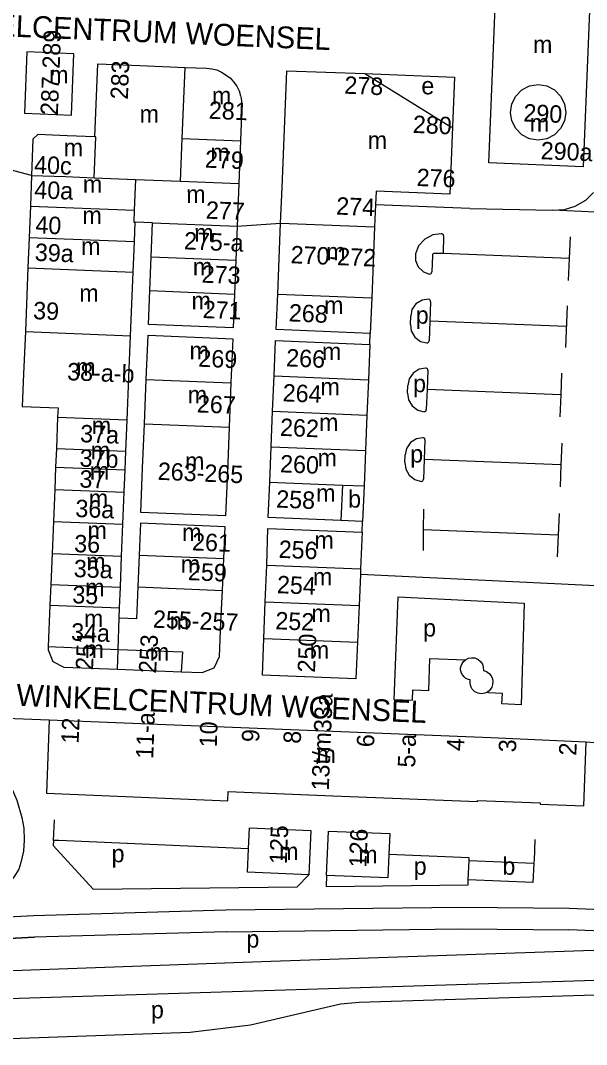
# Model space of a CAD drawing. Extents: x 159675 to 162108, y 386471 to 388472.
# Drawn here: x 161135.6 to 161265.7, y 386484.1 to 386719.4 of the extents above; entities that cross this region are included whole.
import ezdxf

# ---------------------------------------------------------------- set-up
doc = ezdxf.new("R2010")
doc.units = 0
for name, color, linetype in [('BLT_Basislijn', 7, 'Continuous'), ('BLT_Bebouwing', 7, 'Continuous'), ('BLT_Centroide', 7, 'Continuous'), ('BLT_Huisnummer', 7, 'Continuous'), ('BLT_Huisnummer_ tussenligend', 7, 'Continuous'), ('BLT_Huisnummer_reeks', 7, 'Continuous'), ('BLT_Onderverdeling_panden', 7, 'Continuous'), ('BLT_Straatnaam', 7, 'Continuous'), ('BLT_Vlakafsluiter', 7, 'Continuous')]:
    doc.layers.add(name, color=color, linetype=linetype)

msp = doc.modelspace()

# ---------------------------------------------------------------- linework, layer by layer
at = {"layer": 'BLT_Basislijn'}
for p, q in [((161238.9, 386676.16), (161217.2, 386677.02)), ((161261.9, 386669.65), (161261.7, 386664.65)), ((161261.7, 386664.65), (161232.74, 386665.8)), ((161230.28, 386665.38), (161230.15, 386661.59)), ((161261.7, 386664.65), (161261.5, 386659.66)), ((161229.86, 386654.77), (161229.69, 386650.33)), ((161261.27, 386653.85), (161260.89, 386644.21)), ((161225.23, 386649.56), (161225.3, 386651.45)), ((161229.69, 386650.33), (161229.51, 386645.78)), ((161261.08, 386649.08), (161229.69, 386650.33)), ((161215.89, 386644.97), (161216.01, 386647.46)), ((161228.89, 386639.5), (161228.74, 386639.5)), ((161229.21, 386639), (161229.04, 386634.56)), ((161259.98, 386638.33), (161259.78, 386633.34)), ((161224.58, 386633.74), (161224.65, 386635.55)), ((161229.04, 386634.56), (161228.86, 386629.99)), ((161259.78, 386633.34), (161229.04, 386634.56)), ((161259.78, 386633.34), (161259.58, 386628.34)), ((161228.24, 386623.5), (161228.08, 386623.51)), ((161228.56, 386623), (161228.38, 386618.51)), ((161260.02, 386622.26), (161259.82, 386617.26)), ((161223.93, 386617.82), (161224.02, 386619.57)), ((161228.38, 386618.51), (161228.2, 386613.99)), ((161259.82, 386617.26), (161228.38, 386618.51)), ((161259.82, 386617.26), (161259.62, 386612.26)), ((161228.24, 386607.13), (161228.19, 386602.36)), ((161259.38, 386606.13), (161259.18, 386601.13)), ((161214.14, 386601.81), (161214.24, 386604.3)), ((161228.19, 386602.36), (161228.15, 386597.59)), ((161259.18, 386601.13), (161228.19, 386602.36)), ((161259.18, 386601.13), (161258.98, 386596.14)), ((161339.15, 386586.03), (161213.72, 386592.09)), ((161143.21, 386531.02), (161143.43, 386535.77)), ((161261.72, 386515.44), (161288.25, 386514.48)), ((161288.04, 386509.49), (161261.61, 386510.44)), ((161182.92, 386510.03), (161138.83, 386508.8))]:
    msp.add_line(p, q, dxfattribs=at)
for points in [[(161214.78, 386707.15), (161235.37, 386706.31), (161234.9, 386694.91)], [(161257.9, 386675.78), (161260.62, 386675.93), (161263.1, 386676.69), (161265.52, 386678.11), (161267.33, 386679.85)], [(161238.9, 386676.16), (161257.9, 386675.78)], [(161232.31, 386670.39), (161230.35, 386670.13), (161228.5, 386669.15), (161227.1, 386667.59), (161226.36, 386665.76)], [(161232.63, 386670.31), (161232.55, 386670.34), (161232.47, 386670.36), (161232.39, 386670.38), (161232.31, 386670.39)], [(161232.86, 386669.88), (161232.74, 386665.8), (161230.82, 386665.86)], [(161232.86, 386669.88), (161232.85, 386670), (161232.8, 386670.12), (161232.73, 386670.23), (161232.63, 386670.31)], [(161226.36, 386665.76), (161226.36, 386664.25), (161227.01, 386662.75), (161228.2, 386661.63), (161229.62, 386661.11)], [(161230.82, 386665.86), (161230.63, 386665.84), (161230.44, 386665.74), (161230.32, 386665.57), (161230.28, 386665.38)], [(161229.62, 386661.11), (161229.81, 386661.14), (161229.98, 386661.24), (161230.1, 386661.41), (161230.15, 386661.59)], [(161229.4, 386655.31), (161227.91, 386655.15), (161226.48, 386654.3), (161225.56, 386652.94), (161225.3, 386651.45)], [(161229.86, 386654.77), (161229.85, 386654.96), (161229.75, 386655.14), (161229.59, 386655.27), (161229.4, 386655.31)], [(161225.23, 386649.56), (161225.4, 386648.05), (161226.22, 386646.62), (161227.55, 386645.64), (161229.02, 386645.29)], [(161229.02, 386645.29), (161229.2, 386645.33), (161229.36, 386645.44), (161229.47, 386645.6), (161229.51, 386645.78)], [(161228.74, 386639.5), (161227.25, 386639.25), (161225.87, 386638.38), (161224.96, 386637.03), (161224.65, 386635.55)], [(161229.21, 386639), (161229.22, 386639.16), (161229.15, 386639.31), (161229.03, 386639.44), (161228.89, 386639.5)], [(161224.58, 386633.74), (161224.77, 386632.23), (161225.59, 386630.81), (161226.92, 386629.84), (161228.39, 386629.49)], [(161228.39, 386629.49), (161228.56, 386629.53), (161228.73, 386629.64), (161228.83, 386629.81), (161228.86, 386629.99)], [(161228.08, 386623.51), (161226.6, 386623.26), (161225.23, 386622.39), (161224.32, 386621.04), (161224.02, 386619.57)], [(161228.56, 386623), (161228.56, 386623.16), (161228.5, 386623.32), (161228.38, 386623.44), (161228.24, 386623.5)], [(161223.93, 386617.82), (161224.15, 386616.32), (161224.96, 386614.9), (161226.25, 386613.9), (161227.71, 386613.47)], [(161227.71, 386613.47), (161227.9, 386613.5), (161228.07, 386613.62), (161228.18, 386613.8), (161228.2, 386613.99)], [(161222.33, 386586.94), (161221.39, 386563.4), (161225.71, 386563.21), (161225.79, 386565.61), (161229.44, 386565.47), (161229.71, 386572.83), (161237.86, 386572.51)], [(161222.33, 386586.94), (161251.38, 386585.5), (161250.65, 386562.18), (161246.26, 386562.36), (161246.36, 386564.74), (161243.15, 386564.92), (161243.01, 386565.15)], [(161243.01, 386565.15), (161242.69, 386564.97), (161242.3, 386564.82), (161241.94, 386564.74), (161241.55, 386564.71), (161241.13, 386564.74), (161240.78, 386564.83), (161240.44, 386564.96), (161240.06, 386565.18), (161239.75, 386565.43), (161239.43, 386565.79), (161239.17, 386566.23), (161239, 386566.7), (161238.93, 386567.13), (161238.94, 386567.57), (161238.98, 386567.87), (161238.55, 386567.97), (161237.99, 386568.22), (161237.54, 386568.57), (161237.11, 386569.13), (161236.88, 386569.65), (161236.77, 386570.21), (161236.77, 386570.62), (161236.86, 386571.1), (161237.08, 386571.64), (161237.42, 386572.12), (161237.86, 386572.51)], [(161237.86, 386572.51), (161238.56, 386572.87), (161239.27, 386572.99), (161240.02, 386572.92), (161240.78, 386572.59), (161241.31, 386572.15), (161241.76, 386571.48), (161241.97, 386570.8), (161241.98, 386570.06), (161242.7, 386569.81), (161243.31, 386569.39), (161243.79, 386568.8), (161244.08, 386568.15), (161244.19, 386567.49), (161244.12, 386566.8), (161243.94, 386566.25), (161243.66, 386565.78), (161243.31, 386565.39), (161243.01, 386565.15)], [(161143.21, 386531.02), (161143.15, 386529.87), (161152.35, 386519.82), (161199.21, 386520.34), (161201.89, 386523.11)], [(161188.01, 386529.08), (161144.39, 386530.97), (161143.21, 386531.02)], [(161253.55, 386525.76), (161253.73, 386526.41), (161253.92, 386531.23)], [(161238.72, 386526.37), (161238.75, 386527.03), (161220.28, 386527.8)], [(161205.97, 386522.96), (161205.86, 386520.4), (161238.48, 386520.79), (161238.53, 386521.93)], [(161182.82, 386515.03), (161236.89, 386515.67), (161261.72, 386515.44)], [(161109.08, 386511.16), (161122.36, 386512.92), (161138.63, 386513.79), (161182.82, 386515.03)], [(161182.92, 386510.03), (161236.89, 386510.67), (161261.61, 386510.44)], [(161182.96, 386510.03), (161138.83, 386508.8), (161122.82, 386507.94), (161105.19, 386505.61), (161094.47, 386504.99), (161082.47, 386504.72), (161064.43, 386504.23), (161051.3, 386504.09)], [(161093.24, 386504.92), (161105.19, 386505.61), (161122.82, 386507.94), (161138.83, 386508.8)], [(161093.48, 386499.86), (161114.65, 386500.44), (161193.13, 386503.27), (161323.46, 386507.7)], [(161324.17, 386500.57), (161157.3, 386495.37), (161093.79, 386493.39)], [(161094.24, 386484.13), (161174.59, 386486.96), (161188.48, 386488.62), (161209.16, 386493.49), (161213.42, 386493.85), (161324.27, 386497.31)]]:
    msp.add_lwpolyline(points, dxfattribs=at)
at = {"layer": 'BLT_Bebouwing'}
for p, q in [((161152.72, 386692.64), (161146.31, 386692.9)), ((161138.18, 386683.79), (161137.9, 386676.7)), ((161137.9, 386676.7), (161137.61, 386669.53)), ((161161.78, 386668.58), (161161.96, 386673.04)), ((161137.61, 386669.53), (161137.33, 386662.51)), ((161161.5, 386661.56), (161161.78, 386668.58)), ((161137.33, 386662.51), (161136.74, 386647.91)), ((161160.91, 386646.96), (161161.5, 386661.56)), ((161160.52, 386637.41), (161160.91, 386646.96)), ((161160.12, 386627.65), (161160.52, 386637.41)), ((161159.83, 386620.42), (161160.12, 386627.65)), ((161159.65, 386616.15), (161159.83, 386620.42)), ((161159.45, 386611.01), (161159.65, 386616.15)), ((161159.15, 386603.64), (161159.45, 386611.01)), ((161158.85, 386596.31), (161159.15, 386603.64)), ((161158.56, 386589.19), (161158.85, 386596.31)), ((161158.37, 386584.46), (161158.56, 386589.19)), ((161265.58, 386553.55), (161243.74, 386554.54)), ((161238.53, 386521.93), (161238.72, 386526.37)), ((161238.72, 386526.37), (161253.55, 386525.76))]:
    msp.add_line(p, q, dxfattribs=at)
msp.add_lwpolyline([(161243.24, 386686.66), (161245.41, 386739.49), (161267.09, 386738.62), (161264.93, 386685.78)], close=True, dxfattribs=at)
for points in [[(161137.07, 386712.16), (161136.52, 386698.08), (161147.34, 386697.64), (161147.89, 386711.74), (161137.07, 386712.16)], [(161152.72, 386692.64), (161153.4, 386709.39), (161163.05, 386709.01)], [(161163.05, 386709.01), (161173.43, 386708.6)], [(161173.43, 386708.6), (161178.38, 386708.41), (161179.56, 386708.28), (161180.72, 386707.99), (161181.82, 386707.52), (161183.78, 386706.18), (161184.19, 386705.74), (161184.6, 386705.3), (161185.31, 386704.25), (161185.84, 386703.18), (161186.21, 386702.04), (161186.31, 386701.45), (161186.41, 386700.86), (161186.45, 386699.8), (161186.14, 386691.69)], [(161196.26, 386694.39), (161196.8, 386707.78), (161214.78, 386707.15)], [(161214.78, 386707.15), (161234.48, 386694.93), (161234.9, 386694.91)], [(161254.58, 386691.9), (161252.61, 386692.21), (161250.84, 386693.11), (161249.43, 386694.52), (161248.52, 386696.3), (161248.21, 386698.26), (161248.52, 386700.23), (161249.43, 386702.01), (161250.84, 386703.41), (161252.61, 386704.32), (161254.58, 386704.63), (161256.54, 386704.32), (161258.32, 386703.41), (161259.73, 386702.01), (161260.63, 386700.23), (161260.94, 386698.26), (161260.63, 386696.3), (161259.73, 386694.52), (161258.32, 386693.11), (161256.54, 386692.21), (161254.58, 386691.9)], [(161195.72, 386681), (161196.26, 386694.39)], [(161234.9, 386694.91), (161234.27, 386679.43), (161217.32, 386680.12)], [(161146.31, 386692.9), (161139.63, 386693.17), (161138.47, 386692.09), (161138.18, 386683.79)], [(161186.14, 386691.69), (161185.77, 386681.9)], [(161185.77, 386681.9), (161185.39, 386672.09)], [(161195.39, 386672.83), (161195.72, 386681)], [(161217.32, 386680.12), (161217.2, 386677.02)], [(161217.2, 386677.02), (161216.99, 386671.96)], [(161165.98, 386672.88), (161161.96, 386673.04)], [(161165.67, 386665.09), (161165.98, 386672.88)], [(161195.06, 386664.67), (161195.39, 386672.83)], [(161185.39, 386672.09), (161185.1, 386664.31)], [(161216.99, 386671.96), (161216.66, 386663.8)], [(161165.35, 386657.31), (161165.67, 386665.09)], [(161185.1, 386664.31), (161184.8, 386656.52)], [(161194.73, 386656.51), (161195.06, 386664.67)], [(161216.66, 386663.8), (161216.34, 386655.64)], [(161184.8, 386656.52), (161184.5, 386648.74), (161165.04, 386649.53), (161165.35, 386657.31)], [(161194.4, 386648.34), (161194.73, 386656.51)], [(161216.34, 386655.64), (161216.01, 386647.46)], [(161136.74, 386647.91), (161136.33, 386638.18)], [(161164.52, 386636.89), (161164.93, 386647.04), (161184.4, 386646.25), (161183.99, 386636.1)], [(161216.01, 386647.46), (161194.4, 386648.34)], [(161193.88, 386637.71), (161194.21, 386645.85), (161215.89, 386644.97)], [(161215.89, 386644.97), (161215.56, 386636.84)], [(161136.33, 386638.18), (161136.02, 386630.69), (161144.24, 386630.36), (161144.15, 386628.27)], [(161193.55, 386629.58), (161193.88, 386637.71)], [(161164.11, 386626.71), (161164.52, 386636.89)], [(161183.99, 386636.1), (161183.58, 386625.93)], [(161215.56, 386636.84), (161215.23, 386628.71)], [(161144.15, 386628.27), (161143.86, 386621.05)], [(161193.22, 386621.45), (161193.55, 386629.58)], [(161215.23, 386628.71), (161214.9, 386620.57)], [(161163.69, 386616.54), (161164.11, 386626.71)], [(161183.58, 386625.93), (161183.16, 386615.76)], [(161143.86, 386621.05), (161143.68, 386616.78)], [(161192.89, 386613.31), (161193.22, 386621.45)], [(161214.9, 386620.57), (161214.57, 386612.44)], [(161143.68, 386616.78), (161143.48, 386611.64)], [(161183.16, 386615.76), (161182.75, 386605.57), (161163.28, 386606.37), (161163.69, 386616.54)], [(161143.48, 386611.64), (161143.17, 386604.26)], [(161209.25, 386604.51), (161192.56, 386605.18), (161192.89, 386613.31)], [(161214.57, 386612.44), (161214.24, 386604.3)], [(161214.24, 386604.3), (161209.25, 386604.51)], [(161143.17, 386604.26), (161142.88, 386596.93)], [(161182.33, 386595.77), (161182.65, 386603.08), (161163.18, 386603.88), (161162.88, 386596.55)], [(161192.22, 386594.25), (161192.46, 386602.68), (161214.14, 386601.81)], [(161214.14, 386601.81), (161213.77, 386593.38)], [(161142.88, 386596.93), (161142.59, 386589.81)], [(161162.88, 386596.55), (161162.59, 386589.23)], [(161182.01, 386588.44), (161182.33, 386595.77)], [(161191.88, 386585.83), (161192.22, 386594.25)], [(161213.77, 386593.38), (161213.72, 386592.09)], [(161213.72, 386592.09), (161213.41, 386584.96)], [(161142.59, 386589.81), (161142.39, 386585.08)], [(161162.59, 386589.23), (161162.29, 386581.89)], [(161181.69, 386581.11), (161182.01, 386588.44)], [(161191.51, 386577.42), (161191.88, 386585.83)], [(161142.39, 386585.08), (161142, 386575.52)], [(161158.27, 386582.06), (161158.37, 386584.46)], [(161213.41, 386584.96), (161213.04, 386576.55)], [(161162.29, 386581.89), (161158.27, 386582.06)], [(161172.57, 386569.75), (161177.33, 386569.56), (161180.09, 386570.63), (161181.35, 386573.28), (161181.69, 386581.11)], [(161213.04, 386576.55), (161212.67, 386568.14), (161191.2, 386569.01), (161191.51, 386577.42)], [(161142, 386575.52), (161141.97, 386574.79), (161143.02, 386572.12), (161145.57, 386570.83), (161157.91, 386570.34)], [(161157.91, 386570.34), (161172.57, 386569.75)], [(161142.24, 386558.64), (161141.57, 386541.87), (161183.23, 386540.1), (161183.32, 386542.28), (161207.36, 386541.29)], [(161243.74, 386554.54), (161142.24, 386558.64)], [(161240.65, 386539.97), (161240.66, 386540.21), (161255.06, 386539.61), (161255.05, 386539.37), (161265.11, 386538.96), (161265.58, 386553.55)], [(161132.17, 386545.48), (161133.47, 386543.27), (161134.77, 386540.29), (161135.9, 386536.28), (161136.36, 386533.82), (161136.43, 386531.09), (161136.28, 386528.58), (161135.71, 386525.93), (161135.23, 386524.44), (161134.49, 386523.16), (161133.59, 386521.95), (161132.43, 386520.94), (161130.34, 386520.02), (161128.39, 386519.86), (161126.37, 386520.18), (161124.41, 386521.19), (161119.69, 386521.37), (161118.03, 386520.23), (161116.11, 386519.61), (161113.9, 386519.59), (161112.17, 386520.1), (161110.3, 386521.1), (161109.07, 386522.35), (161108.35, 386523.35)], [(161207.36, 386541.29), (161240.65, 386539.97)], [(161188.01, 386529.08), (161188.21, 386533.89), (161202.3, 386533.32), (161201.89, 386523.11)], [(161205.97, 386522.96), (161206.39, 386533.16), (161220.47, 386532.6), (161220.28, 386527.8)], [(161201.89, 386523.11), (161187.79, 386523.69), (161188.01, 386529.08)], [(161220.28, 386527.8), (161220.06, 386522.38), (161205.97, 386522.96)], [(161253.55, 386525.76), (161253.34, 386521.32), (161238.53, 386521.93)]]:
    msp.add_lwpolyline(points, dxfattribs=at)
at = {"layer": 'BLT_Onderverdeling_panden'}
for p, q in [((161172.78, 386692.23), (161173.43, 386708.6)), ((161172.4, 386682.44), (161172.78, 386692.23)), ((161172.78, 386692.23), (161186.14, 386691.69)), ((161162.02, 386682.86), (161172.4, 386682.44)), ((161172.4, 386682.44), (161185.77, 386681.9)), ((161137.9, 386676.7), (161161.74, 386675.76)), ((161165.98, 386672.88), (161185.39, 386672.09)), ((161195.39, 386672.83), (161216.99, 386671.96)), ((161137.61, 386669.53), (161161.78, 386668.58)), ((161165.67, 386665.09), (161185.1, 386664.31)), ((161137.33, 386662.51), (161161.5, 386661.56)), ((161165.35, 386657.31), (161184.8, 386656.52)), ((161194.73, 386656.51), (161216.34, 386655.64)), ((161136.74, 386647.91), (161160.91, 386646.96)), ((161193.88, 386637.71), (161215.56, 386636.84)), ((161164.52, 386636.89), (161183.99, 386636.1)), ((161144.15, 386628.27), (161160.12, 386627.65)), ((161193.55, 386629.58), (161215.23, 386628.71)), ((161164.11, 386626.71), (161183.58, 386625.93)), ((161143.86, 386621.05), (161159.83, 386620.42)), ((161193.22, 386621.45), (161214.9, 386620.57)), ((161143.68, 386616.78), (161159.65, 386616.15)), ((161143.48, 386611.64), (161159.45, 386611.01)), ((161192.89, 386613.31), (161209.58, 386612.64)), ((161209.58, 386612.64), (161214.57, 386612.44)), ((161143.17, 386604.26), (161159.15, 386603.64)), ((161142.88, 386596.93), (161158.85, 386596.31)), ((161162.88, 386596.55), (161182.33, 386595.77)), ((161192.22, 386594.25), (161213.77, 386593.38)), ((161142.59, 386589.81), (161158.56, 386589.19)), ((161162.59, 386589.23), (161182.01, 386588.44)), ((161191.88, 386585.83), (161213.41, 386584.96)), ((161142.39, 386585.08), (161158.37, 386584.46)), ((161191.51, 386577.42), (161213.04, 386576.55))]:
    msp.add_line(p, q, dxfattribs=at)
for points in [[(161152.55, 386683.23), (161152.92, 386692.63), (161152.72, 386692.64)], [(161138.18, 386683.79), (161145.94, 386683.49)], [(161145.94, 386683.49), (161152.55, 386683.23)], [(161152.55, 386683.23), (161162.02, 386682.86)], [(161162.02, 386682.86), (161161.74, 386675.76)], [(161161.74, 386675.76), (161161.63, 386673.05), (161161.96, 386673.04)], [(161209.58, 386612.64), (161209.25, 386604.51)], [(161158.05, 386574.89), (161158.27, 386582.06)], [(161142, 386575.52), (161158.05, 386574.89)], [(161157.91, 386570.34), (161158.05, 386574.89)], [(161158.05, 386574.89), (161172.81, 386574.3), (161172.57, 386569.75)]]:
    msp.add_lwpolyline(points, dxfattribs=at)
at = {"layer": 'BLT_Vlakafsluiter'}
for p, q in [((161138.18, 386683.79), (161126.5, 386686.79)), ((161288.29, 386674.46), (161257.9, 386675.78)), ((161185.39, 386672.09), (161195.39, 386672.83)), ((161142.24, 386558.64), (161128.54, 386559.14)), ((161267.52, 386553.43), (161265.58, 386553.55))]:
    msp.add_line(p, q, dxfattribs=at)

# ---------------------------------------------------------------- texts
at = {"layer": 'BLT_Centroide'}
for s, p in [('m', (161253.39, 386711.87)), ('m', (161142.2, 386704.91)), ('e', (161227.74, 386702.39)), ('m', (161179.61, 386700.11)), ('m', (161162.98, 386695.91)), ('m', (161252.65, 386693.86)), ('m', (161215.41, 386689.88)), ('m', (161145.54, 386688.19)), ('m', (161179.27, 386687.06)), ('m', (161149.95, 386679.78)), ('m', (161173.7, 386677.47)), ('m', (161149.84, 386672.62)), ('m', (161175.54, 386668.59)), ('m', (161149.55, 386665.53)), ('m', (161205.87, 386664.25)), ('m', (161175.23, 386660.81)), ('m', (161149.12, 386654.75)), ('m', (161174.92, 386653.03)), ('m', (161205.37, 386651.97)), ('p', (161226.45, 386649.71)), ('m', (161174.46, 386641.56)), ('m', (161204.89, 386641.34)), ('m', (161148.42, 386637.78)), ('m', (161204.55, 386633.22)), ('p', (161225.83, 386633.98)), ('m', (161174.05, 386631.41)), ('m', (161204.22, 386625.06)), ('m', (161151.99, 386624.34)), ('m', (161151.76, 386618.59)), ('m', (161173.42, 386616.16)), ('m', (161203.89, 386616.94)), ('p', (161225.18, 386617.81)), ('m', (161151.56, 386613.91)), ('m', (161203.56, 386608.81)), ('b', (161210.91, 386607.46)), ('m', (161151.31, 386607.62)), ('m', (161151.02, 386600.28)), ('m', (161172.76, 386599.81)), ('m', (161203.16, 386598.03)), ('m', (161150.72, 386593.06)), ('m', (161172.45, 386592.5)), ('m', (161202.82, 386589.59)), ('m', (161150.47, 386587.12)), ('m', (161202.46, 386581.19)), ('m', (161150.2, 386580)), ('m', (161169.9, 386579.41)), ('p', (161228.14, 386577.84)), ('m', (161150.34, 386572.94)), ('m', (161165.34, 386572.31)), ('m', (161202.11, 386572.78)), ('m', (161203.63, 386548.81)), ('m', (161195.05, 386526.5)), ('p', (161156.55, 386525.99)), ('m', (161213.23, 386525.78)), ('b', (161246.36, 386523.12)), ('p', (161225.98, 386523.12)), ('p', (161187.53, 386506.39)), ('p', (161165.59, 386490.13))]:
    msp.add_text(s, height=4, dxfattribs=at).set_placement(p)
at = {"layer": 'BLT_Huisnummer'}
for s, rotation, p in [('283', 87.7477, (161160.28, 386701.16)), ('281', 357.6852, (161178.83, 386696.8)), ('279', 357.6853, (161177.94, 386685.57)), ('40c', 357.7539, (161138.68, 386684.28)), ('40a', 357.7539, (161138.73, 386678.54)), ('277', 357.6852, (161178.15, 386673.86)), ('40', 357.7539, (161138.98, 386670.47)), ('39a', 357.7561, (161138.85, 386664.16)), ('39', 357.7561, (161138.46, 386650.77)), ('271', 357.6852, (161177.42, 386651.02)), ('268', 357.6544, (161197.22, 386650.25)), ('269', 357.6852, (161176.43, 386639.84)), ('266', 357.684, (161196.61, 386639.92)), ('37a', 357.7553, (161149.27, 386622.5)), ('262', 357.689, (161195.2, 386623.96)), ('37b', 357.755, (161149.15, 386616.89)), ('37', 357.7551, (161149.11, 386612.09)), ('36a', 357.7551, (161148.17, 386605.32)), ('258', 357.689, (161194.32, 386607.49)), ('36', 357.7549, (161147.9, 386597.25)), ('261', 357.6853, (161174.98, 386597.65)), ('256', 357.6863, (161194.88, 386595.94)), ('35a', 357.7549, (161147.8, 386591.52)), ('35', 357.7549, (161147.47, 386585.5)), ('34a', 357.7547, (161147.18, 386576.95)), ('251', 87.5044, (161152.27, 386570.07)), ('253', 86.8927, (161166.77, 386569.3)), ('250', 87.6858, (161203.28, 386569.51)), ('125', 87.7271, (161196.8, 386525.49)), ('126', 87.7271, (161215.09, 386524.73))]:
    msp.add_text(s, height=4, rotation=rotation, dxfattribs=at).set_placement(p)
at = {"layer": 'BLT_Huisnummer_ tussenligend'}
for s, rotation, p in [('273', 357.6859, (161177.19, 386659.15)), ('264', 357.689, (161195.81, 386631.88)), ('267', 357.6853, (161176.09, 386629.34)), ('260', 357.689, (161195.21, 386615.58)), ('259', 357.6857, (161174.03, 386590.82)), ('254', 357.6861, (161194.49, 386587.82)), ('252', 357.6858, (161194.12, 386579.53))]:
    msp.add_text(s, height=4, rotation=rotation, dxfattribs=at).set_placement(p)
at = {"layer": 'BLT_Huisnummer_reeks'}
for s, rotation, p in [('287-289', 87.7576, (161144.19, 386697.54)), ('278', 357.6694, (161209.98, 386702.56)), ('290', 357.6876, (161251.12, 386696.18)), ('280', 357.6881, (161225.72, 386693.55)), ('290a', 357.6876, (161255.1, 386687.51)), ('276', 357.6881, (161226.59, 386681.36)), ('274', 357.6882, (161208.11, 386674.79)), ('275-a', 357.6836, (161173.13, 386666.8)), ('270-272', 357.6883, (161197.63, 386663.61)), ('38-a-b', 357.7553, (161146.29, 386636.74)), ('263-265', 357.6476, (161167.1, 386613.86)), ('255-257', 357.6848, (161165.99, 386579.89)), ('13t/m33a', 87.6486, (161206.46, 386542.44)), ('11-a', 87.9259, (161166.11, 386549.69)), ('12', 87.6486, (161148.96, 386553.17)), ('10', 87.9259, (161180.71, 386552.33)), ('9', 87.706, (161190.44, 386553.52)), ('8', 87.6486, (161200.01, 386553.16)), ('6', 87.9396, (161216.86, 386552.37)), ('5-a', 88.1228, (161226.3, 386547.7)), ('4', 88.1228, (161237.53, 386551.49)), ('3', 88.1228, (161249.49, 386551.2)), ('2', 87.2438, (161263.32, 386550.41))]:
    msp.add_text(s, height=4, rotation=rotation, dxfattribs=at).set_placement(p)
at = {"layer": 'BLT_Straatnaam'}
for p in [(161112.55, 386716.53), (161134.57, 386561.96)]:
    msp.add_text('WINKELCENTRUM WOENSEL', height=5, rotation=357.5852, dxfattribs=at).set_placement(p)

doc.saveas('drawing.dxf')
